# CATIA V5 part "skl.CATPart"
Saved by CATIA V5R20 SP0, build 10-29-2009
Part number: skl
Publications: "Longueur.1", "Longueur.2", "Longueur.3", "Point.1", "Point.2", "Point.3", "Point.4", "Point.5", "Point.6", "Droite.1", "Droite.2", "Droite.3", "Plan.1", "Plan.2", "Point.7"
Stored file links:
  D:\Dropbox\IAO_2011\MMS_GR2\IAO_2011_1491_mcabanel\IAO_2011_1491_mcabanel\skl.CATPart

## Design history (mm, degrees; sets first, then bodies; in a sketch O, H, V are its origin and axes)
Parameters
  LENGTH = 190 mm
  LENGTH = 60 mm
  LENGTH = 100 mm
Set1
  Point1: (0, 0, 50)
  Point2: (0, -100 {= -LENGTH}, 0), relative to Point1
  Point3: (-10, 0, 0), relative to Point2
  Point4: (0, -60 {= -LENGTH}, 0), relative to Point3
  Point5: (-10, 0, 0), relative to Point4
  Point6: (0, 190 {= LENGTH}, 0), relative to Point5
  Line1: type PtPt, FirstPoint Point1, SecondPoint Point2
  Line2: type PtPt, FirstPoint Point3, SecondPoint Point4
  Line3: type PtPt, FirstPoint Point6, SecondPoint Point5
  Plane1: type OffsetPt, RefPlane yz-plane, RefPoint Point3
  Plane2: type OffsetPt, RefPlane yz-plane, RefPoint Point5
  Point7: (-10, 40, 50)
Body1 (main body)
